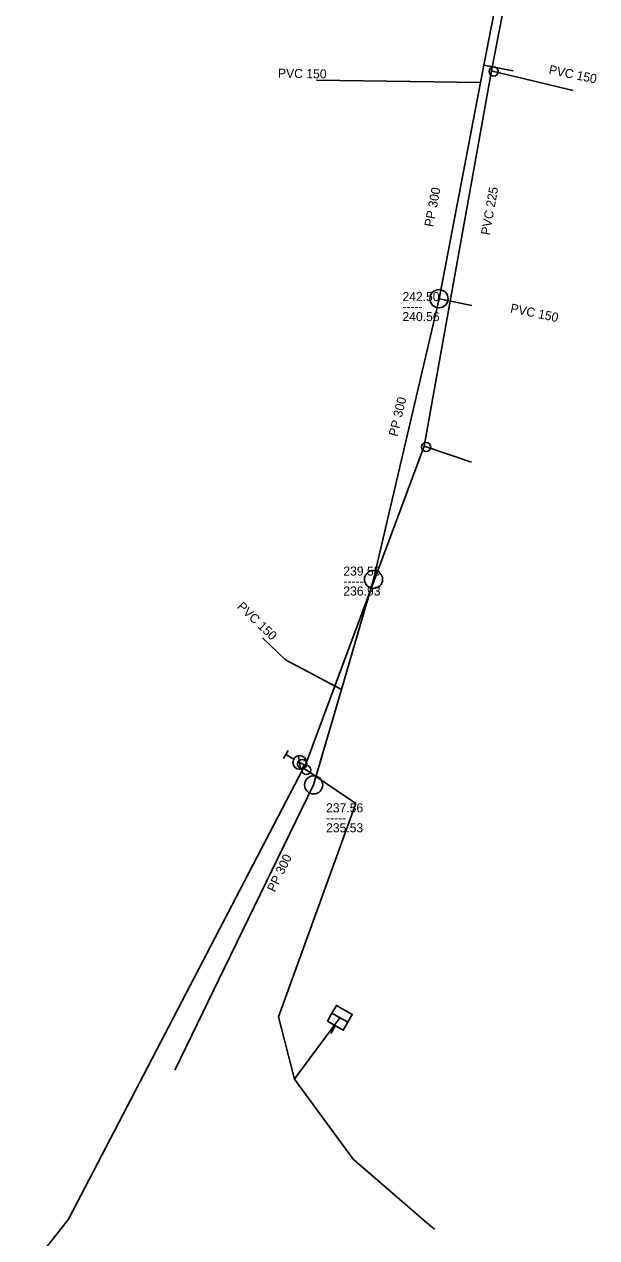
# Model space of a CAD drawing. Extents: x -770828 to -770111, y -1050344 to -1049447.
# Drawn here: x -770754 to -770690.9, y -1050195 to -1050061.2 of the extents above; entities that cross this region are included whole.
import ezdxf

# ---------------------------------------------------------------- set-up
doc = ezdxf.new("R2010")
doc.units = 0
doc.layers.add('Level 0', color=7, linetype='Continuous')

msp = doc.modelspace()

# ---------------------------------------------------------------- linework, layer by layer
at = {"layer": 'Level 0'}
for p, q in [((-770702.51, -1050066.39), (-770699.54, -1050051.07)), ((-770701.96, -1050058.56), (-770703.34, -1050065.74)), ((-770703.34, -1050065.74), (-770703.71, -1050067.68)), ((-770703.34, -1050065.74), (-770700.13, -1050066.39)), ((-770709.92, -1050107.76), (-770702.51, -1050066.39)), ((-770702.51, -1050066.39), (-770702.25, -1050066.45)), ((-770702.25, -1050066.45), (-770693.49, -1050068.56)), ((-770703.71, -1050067.68), (-770721.78, -1050067.39)), ((-770703.71, -1050067.68), (-770708.28, -1050091.49)), ((-770708.28, -1050091.49), (-770715.49, -1050122.43)), ((-770708.28, -1050091.49), (-770704.65, -1050092.24)), ((-770722.87, -1050142.58), (-770709.92, -1050107.76)), ((-770709.92, -1050107.76), (-770709.7, -1050107.83)), ((-770709.7, -1050107.83), (-770704.69, -1050109.51)), ((-770715.49, -1050122.43), (-770719.03, -1050134.57)), ((-770725.18, -1050131.29), (-770727.72, -1050128.86)), ((-770719.03, -1050134.57), (-770725.18, -1050131.29)), ((-770719.03, -1050134.57), (-770722.09, -1050145.07)), ((-770725.4, -1050142.16), (-770724.9, -1050141.29)), ((-770724.28, -1050142.23), (-770725.15, -1050141.73)), ((-770723.52, -1050143.34), (-770723.74, -1050141.86)), ((-770749.09, -1050192.94), (-770723.23, -1050143.26)), ((-770723.35, -1050142.76), (-770723.63, -1050142.6)), ((-770723.06, -1050142.93), (-770723.35, -1050142.76)), ((-770723.23, -1050143.26), (-770723.06, -1050142.93)), ((-770723.23, -1050143.26), (-770722.9, -1050143.43)), ((-770723.06, -1050142.93), (-770722.87, -1050142.58)), ((-770722.9, -1050143.43), (-770717.45, -1050147.11)), ((-770722.09, -1050145.07), (-770731.91, -1050165.25)), ((-770717.45, -1050147.11), (-770725.96, -1050170.62)), ((-770731.91, -1050165.25), (-770737.39, -1050176.52)), ((-770725.96, -1050170.62), (-770724.19, -1050177.52)), ((-770719.2, -1050170.74), (-770724.03, -1050177.3)), ((-770720.2, -1050172.47), (-770719.7, -1050171.61)), ((-770724.03, -1050177.3), (-770724.19, -1050177.52)), ((-770724.19, -1050177.52), (-770717.73, -1050186.31)), ((-770717.73, -1050186.31), (-770710.99, -1050192.15)), ((-770753.95, -1050199.13), (-770749.09, -1050192.94)), ((-770710.99, -1050192.15), (-770709.89, -1050193.1)), ((-770709.89, -1050193.1), (-770708.79, -1050194.05))]:
    msp.add_line(p, q, dxfattribs=at)
msp.add_lwpolyline([(-770720.07, -1050170.24), (-770719.57, -1050169.37), (-770717.83, -1050170.37), (-770718.33, -1050171.24)], dxfattribs=at)
msp.add_lwpolyline([(-770720.57, -1050171.11), (-770718.83, -1050172.11), (-770718.33, -1050171.24), (-770720.07, -1050170.24)], close=True, dxfattribs=at)
for centre, radius in [((-770702.25, -1050066.45), 0.5), ((-770708.28, -1050091.49), 1), ((-770709.7, -1050107.83), 0.5), ((-770715.49, -1050122.43), 1), ((-770723.63, -1050142.6), 0.75), ((-770723.35, -1050142.76), 0.5), ((-770722.9, -1050143.43), 0.5), ((-770722.09, -1050145.07), 1)]:
    msp.add_circle(centre, radius, dxfattribs=at)

# ---------------------------------------------------------------- texts
for s, rotation, p in [('PVC 150', 348.553, (-770696.26, -1050066.71)), ('PVC 150', 359.081, (-770726.02, -1050067.13)), ('PP 300', 79.12, (-770708.93, -1050083.64)), ('PVC 225', 79.845, (-770702.7, -1050084.54)), ('PVC 150', 348.326, (-770700.49, -1050092.99)), ('PP 300', 76.882, (-770712.86, -1050106.73)), ('PVC 150', 316.268, (-770730.58, -1050125.51)), ('PP 300', 64.051, (-770726.37, -1050156.96))]:
    msp.add_text(s, height=1, rotation=rotation, dxfattribs=at).set_placement(p)
for s, p in [('242.50', (-770712.31, -1050091.76)), ('-----', (-770712.31, -1050092.86)), ('240.56', (-770712.31, -1050093.96)), ('239.55', (-770718.82, -1050122.01)), ('-----', (-770718.82, -1050123.11)), ('236.93', (-770718.82, -1050124.21)), ('237.56', (-770720.72, -1050148.1)), ('-----', (-770720.72, -1050149.2)), ('235.53', (-770720.72, -1050150.3))]:
    msp.add_text(s, height=1, dxfattribs=at).set_placement(p)

doc.saveas('drawing.dxf')
